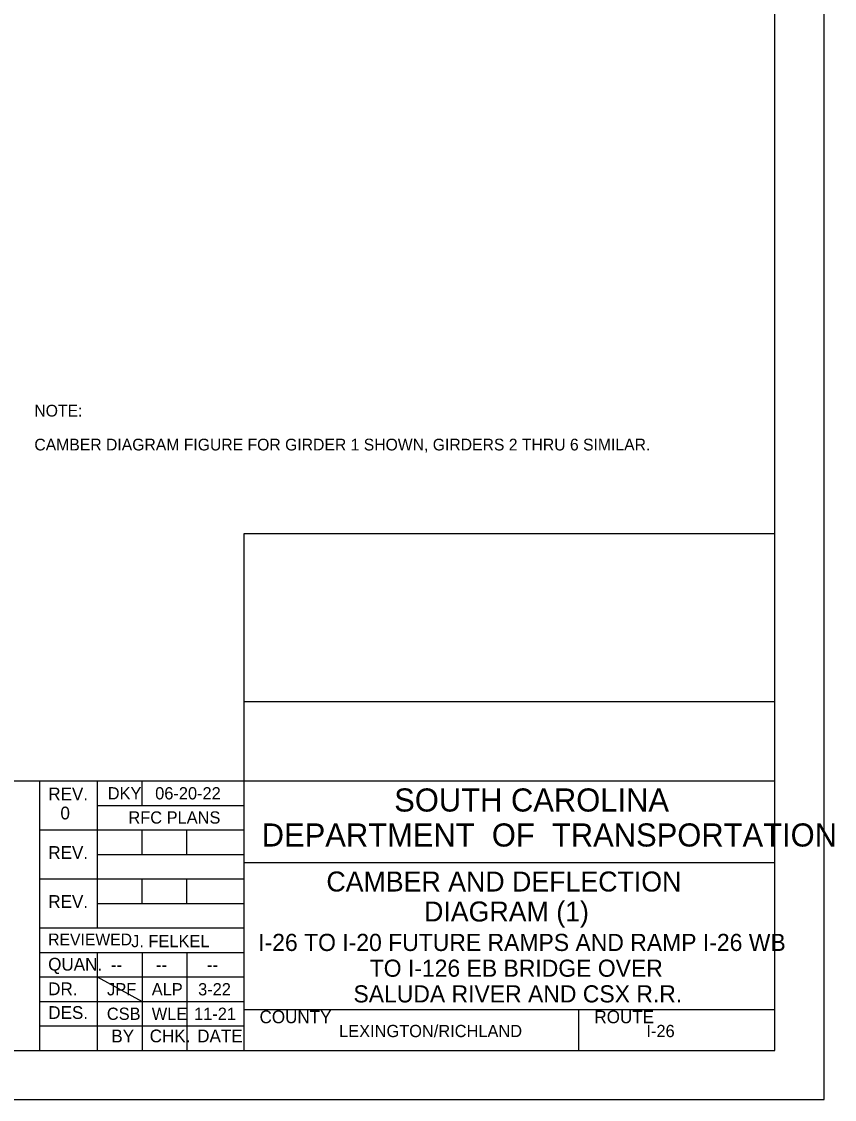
# Model space of a CAD drawing. Extents: x -133.1 to -97, y -1.7 to 20.3.
# Drawn here: x -105.33 to -97.03, y -1.69 to 9.31 of the extents above; entities that cross this region are included whole.
import ezdxf

# ---------------------------------------------------------------- set-up
doc = ezdxf.new("R2010")
doc.units = 0
for name, color, linetype in [('BR_BORDER LINES', 7, 'Continuous'), ('BR_TEXT', 7, 'Continuous'), ('Level 31', 7, 'Continuous')]:
    doc.layers.add(name, color=color, linetype=linetype)

msp = doc.modelspace()

# ---------------------------------------------------------------- linework, layer by layer
at = {"layer": 'BR_BORDER LINES'}
for p, q in [((-97.642, -1.191), (-97.642, 19.809)), ((-103.058, -1.191), (-103.058, 4.086)), ((-103.058, 4.086), (-97.642, 4.086)), ((-103.058, 2.371), (-97.642, 2.371)), ((-110.507, 1.559), (-105.142, 1.559)), ((-105.142, -1.191), (-105.142, 1.559)), ((-105.142, 1.559), (-97.642, 1.559)), ((-104.559, 1.559), (-104.559, 0.059)), ((-104.1, 1.309), (-104.1, 1.559)), ((-104.559, 1.309), (-103.058, 1.309)), ((-105.142, 1.059), (-103.058, 1.059)), ((-104.1, 0.809), (-104.1, 1.059)), ((-103.642, 0.809), (-103.642, 1.059)), ((-104.559, 0.809), (-103.058, 0.809)), ((-103.058, 0.726), (-103.058, 0.726)), ((-103.058, 0.726), (-97.641, 0.726)), ((-105.142, 0.559), (-103.058, 0.559)), ((-104.1, 0.309), (-104.1, 0.559)), ((-103.642, 0.309), (-103.642, 0.559)), ((-104.559, 0.309), (-103.058, 0.309)), ((-105.142, 0.059), (-103.058, 0.059)), ((-105.142, -0.191), (-103.058, -0.191)), ((-104.559, -0.191), (-104.559, -1.191)), ((-104.1, -0.191), (-104.1, -1.191)), ((-103.642, -0.191), (-103.642, -1.191)), ((-105.142, -0.441), (-103.058, -0.441)), ((-105.142, -0.691), (-103.058, -0.691)), ((-103.058, -0.774), (-97.642, -0.774)), ((-102.961, -0.774), (-97.642, -0.774)), ((-99.642, -1.191), (-99.642, -0.774)), ((-105.142, -0.941), (-103.058, -0.941)), ((-131.308, -1.191), (-97.642, -1.191))]:
    msp.add_line(p, q, dxfattribs=at)
at = {"layer": 'Level 31'}
for p, q in [((-100.35, 0.285), (-100.35, 0.285)), ((-104.559, -0.441), (-104.1, -0.691))]:
    msp.add_line(p, q, dxfattribs=at)
msp.add_lwpolyline([(-133.141, -1.691), (-97.141, -1.691), (-97.141, 20.309), (-133.141, 20.309)], close=True, dxfattribs=at)

# ---------------------------------------------------------------- texts
at = {"layer": 'BR_TEXT'}
for s, height, p in [('NOTE:', 0.12, (-105.199, 5.278)), ('CAMBER DIAGRAM FIGURE FOR GIRDER 1 SHOWN, GIRDERS 2 THRU 6 SIMILAR.', 0.12, (-105.199, 4.932)), ('REV.', 0.13, (-105.057, 1.362)), ('DKY', 0.125, (-104.45, 1.371)), ('06-20-22', 0.125, (-103.966, 1.371)), ('SOUTH CAROLINA', 0.23587, (-101.527, 1.247)), ('0', 0.13, (-104.933, 1.167)), ('RFC PLANS', 0.125, (-104.239, 1.124)), ('DEPARTMENT  OF  TRANSPORTATION', 0.23587, (-102.879, 0.89)), ('REV.', 0.13, (-105.057, 0.764)), ('CAMBER AND DEFLECTION', 0.204, (-102.219, 0.431)), ('REV.', 0.13, (-105.057, 0.264)), ('DIAGRAM (1)', 0.204, (-101.222, 0.125)), ('REVIEWED', 0.12, (-105.058, -0.118)), ('I-26 TO I-20 FUTURE RAMPS AND RAMP I-26 WB', 0.175, (-102.915, -0.176)), ('J. FELKEL', 0.125, (-104.211, -0.137)), ('QUAN.', 0.13, (-105.058, -0.376)), ('--', 0.125, (-104.416, -0.379)), ('--', 0.125, (-103.957, -0.379)), ('--', 0.125, (-103.437, -0.379)), ('TO I-126 EB BRIDGE OVER', 0.175, (-101.777, -0.439)), ('DR.', 0.13, (-105.058, -0.627)), ('JPF', 0.125, (-104.457, -0.629)), ('ALP', 0.125, (-104.001, -0.629)), ('3-22', 0.125, (-103.528, -0.629)), ('SALUDA RIVER AND CSX R.R.', 0.175, (-101.943, -0.701)), ('DES.', 0.13, (-105.057, -0.869)), ('CSB', 0.125, (-104.459, -0.879)), ('WLE', 0.125, (-104.001, -0.879)), ('11-21', 0.125, (-103.569, -0.879)), ('COUNTY', 0.13, (-102.901, -0.913)), ('ROUTE', 0.13, (-99.484, -0.913)), ('BY', 0.13, (-104.413, -1.109)), ('CHK.', 0.13, (-104.022, -1.108)), ('DATE', 0.13, (-103.537, -1.108)), ('LEXINGTON/RICHLAND', 0.12499, (-102.089, -1.055)), ('I-26', 0.125, (-98.953, -1.055))]:
    msp.add_text(s, height=height, dxfattribs=at).set_placement(p)

doc.saveas('drawing.dxf')
